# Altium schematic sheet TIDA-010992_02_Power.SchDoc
size 431 x 279 mm; Date: Not shown in title block; ApprovedBy: Not shown in title block; CheckedBy: Not shown in title block; Author: Not shown in title block; CompanyName: Not shown in title block; Engineer: Not shown in title block; Organization: Not shown in title block; Address1: Not shown in title block; Address2: Not shown in title block; Address3: Not shown in title block; Address4: Not shown in title block; DocumentNumber: 2; Revision: Use project parameter SCH_Rev; SheetNumber: 2; SheetTotal: 13; PageSetup: Record=PageOptions¦CenterHorizontal=True¦CenterVertical=True¦PrintScale=1.00¦XCorrection=1.00¦YCorrection=1.00¦PrintKind=0¦BorderSize=5000000¦LeftOffset=0¦BottomOffset=0¦Orientation=2¦PaperLength=1000¦PaperWidth=1000¦Scale=100¦PaperSource=15¦PrintQuality=600¦MediaType=1¦DitherType=10¦PaperKind=Letter¦PrintScaleMode=1
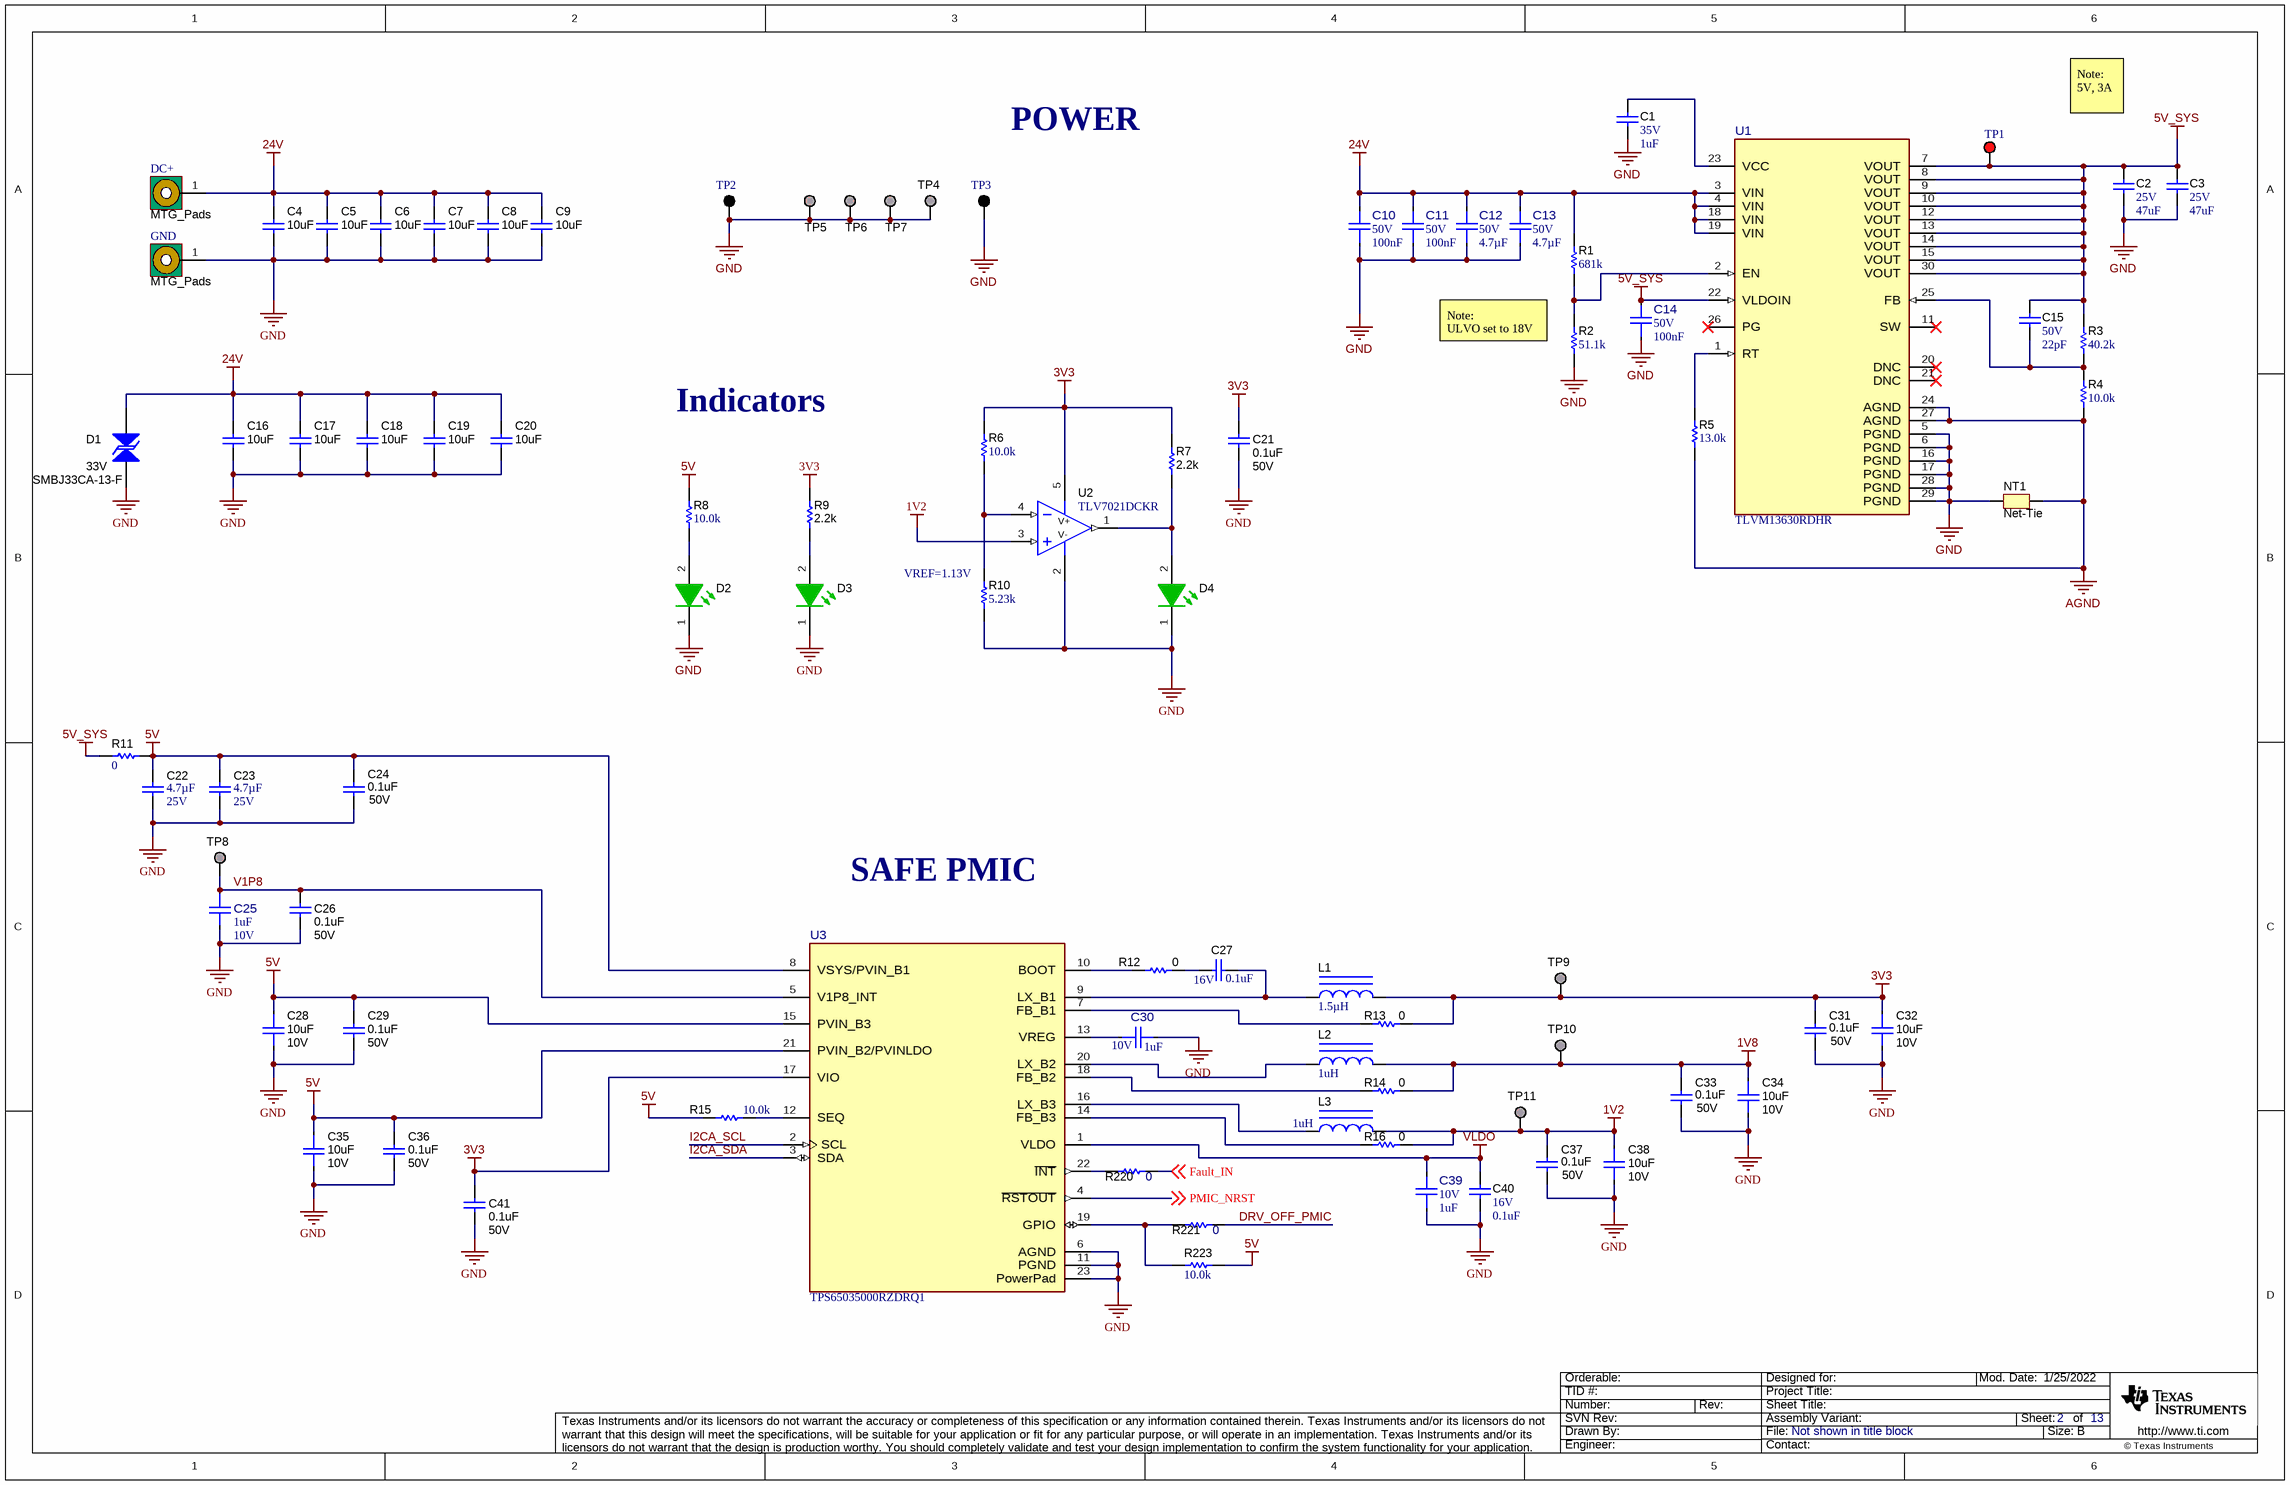
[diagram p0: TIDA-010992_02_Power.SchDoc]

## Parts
C1  VDC_V: 35V  ValueDisplayed: 1uF  [0402L]  (hidden comment: GRM155R6YA105ME11D)
C2  VDC_V: 25V  ValueDisplayed: 47uF  [1206_190]  (hidden comment: C3216X5R1E476M160AC)
C3  VDC_V: 25V  ValueDisplayed: 47uF  [1206_190]  (hidden comment: C3216X5R1E476M160AC)
C4  ValueDisplayed: 10uF  [1210_270L]  (hidden comment: GRM32ER71H106KA12L)
C5  ValueDisplayed: 10uF  [1210_270L]  (hidden comment: GRM32ER71H106KA12L)
C6  ValueDisplayed: 10uF  [1210_270L]  (hidden comment: GRM32ER71H106KA12L)
C7  ValueDisplayed: 10uF  [1210_270L]  (hidden comment: GRM32ER71H106KA12L)
C8  ValueDisplayed: 10uF  [1210_270L]  (hidden comment: GRM32ER71H106KA12L)
C9  ValueDisplayed: 10uF  [1210_270L]  (hidden comment: GRM32ER71H106KA12L)
C10  VDC_V: 50V  ValueDisplayed: 100nF  [FP-885012205086_0402-MFG]  (hidden comment: 885012205086)
C11  VDC_V: 50V  ValueDisplayed: 100nF  [FP-885012205086_0402-MFG]  (hidden comment: 885012205086)
C12  VDC_V: 50V  Cap_F: 4.7µF  [FP-C2012X7R1H475K125AC_0805-MFG]  (hidden comment: C2012X7R1H475K125AC)
C13  VDC_V: 50V  Cap_F: 4.7µF  [FP-C2012X7R1H475K125AC_0805-MFG]  (hidden comment: C2012X7R1H475K125AC)
C14  VDC_V: 50V  ValueDisplayed: 100nF  [FP-885012205086_0402-MFG]  (hidden comment: 885012205086)
C15  VDC_V: 50V  ValueDisplayed: 22pF  [0402L]  (hidden comment: CGA2B2C0G1H220J050BA)
C16  ValueDisplayed: 10uF  [1210_270L]  (hidden comment: GRM32ER71H106KA12L)
C17  ValueDisplayed: 10uF  [1210_270L]  (hidden comment: GRM32ER71H106KA12L)
C18  ValueDisplayed: 10uF  [1210_270L]  (hidden comment: GRM32ER71H106KA12L)
C19  ValueDisplayed: 10uF  [1210_270L]  (hidden comment: GRM32ER71H106KA12L)
C20  ValueDisplayed: 10uF  [1210_270L]  (hidden comment: GRM32ER71H106KA12L)
C21  VDC_V: 50V  ValueDisplayed: 0.1uF  [0402]  (hidden comment: CGA2B3X7R1H104M050BB)
C22  VDC_V: 25V  ValueDisplayed: 4.7µF  [0805L]  (hidden comment: CGA4J1X7R1E475K125AC)
C23  VDC_V: 25V  ValueDisplayed: 4.7µF  [0805L]  (hidden comment: CGA4J1X7R1E475K125AC)
C24  VDC_V: 50V  ValueDisplayed: 0.1uF  [0402]  (hidden comment: CGA2B3X7R1H104M050BB)
C25  VDC_V: 10V  ValueDisplayed: 1uF  [FP-GRM155C71A105KE11D_0402-MFG]  (hidden comment: GRM155C71A105KE11D)
C26  VDC_V: 50V  ValueDisplayed: 0.1uF  [0402]  (hidden comment: CGA2B3X7R1H104M050BB)
C27  VDC_V: 16V  ValueDisplayed: 0.1uF  [0201]  (hidden comment: GRM033Z71C104KE14D)
C28  VDC_V: 10V  ValueDisplayed: 10uF  [FP-CGA4J3X7S1A106K125AE_0805-MFG]  (hidden comment: CGA4J3X7S1A106K125AE)
C29  VDC_V: 50V  ValueDisplayed: 0.1uF  [0402]  (hidden comment: CGA2B3X7R1H104M050BB)
C30  VDC_V: 10V  ValueDisplayed: 1uF  [FP-GRM155C71A105KE11D_0402-MFG]  (hidden comment: GRM155C71A105KE11D)
C31  VDC_V: 50V  ValueDisplayed: 0.1uF  [0402]  (hidden comment: CGA2B3X7R1H104M050BB)
C32  VDC_V: 10V  ValueDisplayed: 10uF  [FP-CGA4J3X7S1A106K125AE_0805-MFG]  (hidden comment: CGA4J3X7S1A106K125AE)
C33  VDC_V: 50V  ValueDisplayed: 0.1uF  [0402]  (hidden comment: CGA2B3X7R1H104M050BB)
C34  VDC_V: 10V  ValueDisplayed: 10uF  [FP-CGA4J3X7S1A106K125AE_0805-MFG]  (hidden comment: CGA4J3X7S1A106K125AE)
C35  VDC_V: 10V  ValueDisplayed: 10uF  [FP-CGA4J3X7S1A106K125AE_0805-MFG]  (hidden comment: CGA4J3X7S1A106K125AE)
C36  VDC_V: 50V  ValueDisplayed: 0.1uF  [0402]  (hidden comment: CGA2B3X7R1H104M050BB)
C37  VDC_V: 50V  ValueDisplayed: 0.1uF  [0402]  (hidden comment: CGA2B3X7R1H104M050BB)
C38  VDC_V: 10V  ValueDisplayed: 10uF  [FP-CGA4J3X7S1A106K125AE_0805-MFG]  (hidden comment: CGA4J3X7S1A106K125AE)
C39  VDC_V: 10V  ValueDisplayed: 1uF  [FP-GRM155C71A105KE11D_0402-MFG]  (hidden comment: GRM155C71A105KE11D)
C40  VDC_V: 16V  ValueDisplayed: 0.1uF  [0201]  (hidden comment: GRM033Z71C104KE14D)
C41  VDC_V: 50V  ValueDisplayed: 0.1uF  [0402]  (hidden comment: CGA2B3X7R1H104M050BB)
D1  SMBJ33CA-13-F  value 33V  [SMB-Bi]
D2  150040GS73240  [WL-SMCC_0402_Green]  (value not drawn)
D3  150040GS73240  [WL-SMCC_0402_Green]  (value not drawn)
D4  150040GS73240  [WL-SMCC_0402_Green]  (value not drawn)
DC+  MTG_Pads  [MTGP_2-48_PanHead]  (no BOM)
GND  MTG_Pads  [MTGP_2-48_PanHead]  (no BOM)
L1  ValueDisplayed: 1.5µH  [TFM201610ALMA]  (hidden comment: TFM201610ALMA1R5MTAA)
L2  ValueDisplayed: 1uH  [TFM201610]  (hidden comment: TFM201610GHM-1R0MTAA)
L3  ValueDisplayed: 1uH  [TFM201610]  (hidden comment: TFM201610GHM-1R0MTAA)
NT1  Net-Tie  [Net-Tie7milsWide_20milsLong]  (net tie, no BOM)
R1  ValueDisplayed: 681k  [0402L]  (hidden comment: CRCW0402681KFKED)
R2  ValueDisplayed: 51.1k  [0402L]  (hidden comment: CRCW040251K1FKED)
R3  ValueDisplayed: 40.2k  [0402L]  (hidden comment: CRCW040240K2FKED)
R4  ValueDisplayed: 10.0k  [0402L]  (hidden comment: CRCW040210K0FKED)
R5  ValueDisplayed: 13.0k  [0402L]  (hidden comment: CRCW040213K0FKED)
R6  ValueDisplayed: 10.0k  [0402L]  (hidden comment: CRCW040210K0FKED)
R7  ValueDisplayed: 2.2k  [0402]  (hidden comment: CRCW04022K20JNED)
R8  ValueDisplayed: 10.0k  [0402L]  (hidden comment: CRCW040210K0FKED)
R9  ValueDisplayed: 2.2k  [0402]  (hidden comment: CRCW04022K20JNED)
R10  ValueDisplayed: 5.23k  [0402]  (hidden comment: CRCW04025K23FKED)
R11  ValueDisplayed: 0  [0603]  (hidden comment: PMR03EZPJ000)
R12  Res_ohm: 0  [FP-RC0201JR-070RL_0201 (0603 Metric)-IPC_C]  (hidden comment: RC0201JR-070RL)
R13  Res_ohm: 0  [FP-RC0201JR-070RL_0201 (0603 Metric)-IPC_C]  (hidden comment: RC0201JR-070RL)
R14  Res_ohm: 0  [FP-RC0201JR-070RL_0201 (0603 Metric)-IPC_C]  (hidden comment: RC0201JR-070RL)
R15  ValueDisplayed: 10.0k  [0402L]  (hidden comment: CRCW040210K0FKED)
R16  Res_ohm: 0  [FP-RC0201JR-070RL_0201 (0603 Metric)-IPC_C]  (hidden comment: RC0201JR-070RL)
R220  ValueDisplayed: 0  [0402]  (hidden comment: CRCW04020000Z0EDHP)
R221  ValueDisplayed: 0  [0402]  (hidden comment: CRCW04020000Z0EDHP)
R223  ValueDisplayed: 10.0k  [0402L]  (hidden comment: CRCW040210K0FKED)
TP1  5000  [Keystone5000]  (value not drawn)
TP2  CMP-0055138-2  [Keystone5001]  (value not drawn)
TP3  CMP-0055138-2  [Keystone5001]  (value not drawn)
TP4  TP_SM_1MM  [TP_SM_1MM]  (value not drawn)  (no BOM)
TP5  TP_SM_1MM  [TP_SM_1MM]  (value not drawn)  (no BOM)
TP6  TP_SM_1MM  [TP_SM_1MM]  (value not drawn)  (no BOM)
TP7  TP_SM_1MM  [TP_SM_1MM]  (value not drawn)  (no BOM)
TP8  TESTPOINT  [TP_25MIL-SMT]  (value not drawn)  (no BOM)
TP9  TESTPOINT  [TP_25MIL-SMT]  (value not drawn)  (no BOM)
TP10  TESTPOINT  [TP_25MIL-SMT]  (value not drawn)  (no BOM)
TP11  TESTPOINT  [TP_25MIL-SMT]  (value not drawn)  (no BOM)
U1  TLVM13630RDHR  [RDH0030A-MFG]
U2  TLV7021DCKR  [DCK0005A_N]
U3  TPS65035000RZDRQ1  [RZD0022A-MFG]

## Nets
1V2: C37.1 C38.1 L3.2 R16.2 TP11.1 U2.3(IN+)
1V8: C33.1 C34.1 L2.2 R14.2 TP10.1
3V3: C21.1 C31.1 C32.1 C41.1 L1.2 R6.1 R7.2 R9.2 R13.2 TP9.1 U2.5(V+) U3.17(VIO)
5V: C22.1 C23.1 C24.1 C28.1 C29.1 C35.1 C36.1 R8.1 R11.1 R15.2 R223.2 U3.8(VSYS/PVIN_B1) U3.15(PVIN_B3) U3.21(PVIN_B2/PVINLDO)
5V_SYS: C2.1 C3.1 C14.2 C15.1 R3.2 R11.2 TP1.1 U1.7(VOUT) U1.8(VOUT) U1.9(VOUT) U1.10(VOUT) U1.12(VOUT) U1.13(VOUT) U1.14(VOUT) U1.15(VOUT) U1.22(VLDOIN) U1.30(VOUT)
24V: C4.2 C5.2 C6.2 C7.2 C8.2 C9.2 C10.2 C11.2 C12.2 C13.2 C16.2 C17.2 C18.2 C19.2 C20.2 D1.2 DC+.1 R1.2 U1.3(VIN) U1.4(VIN) U1.18(VIN) U1.19(VIN)
AGND: NT1.2 R4.1 R5.1 U1.24(AGND) U1.27(AGND)
GND: C1.2 C2.2 C3.2 C4.1 C5.1 C6.1 C7.1 C8.1 C9.1 C10.1 C11.1 C12.1 C13.1 C14.1 C16.1 C17.1 C18.1 C19.1 C20.1 C21.2 C22.2 C23.2 C24.2 C25.2 C26.2 C28.2 C29.2 C30.2 C31.2 C32.2 C33.2 C34.2 C35.2 C36.2 C37.2 C38.2 C39.1 C40.1 C41.2 D1.1 D2.1(K) D3.1(K) D4.1(K) GND.1 NT1.1 R2.1 R10.1 TP2.1 TP3.1 TP4.1 TP5.1 TP6.1 TP7.1 U1.5(PGND) U1.6(PGND) U1.16(PGND) U1.17(PGND) U1.28(PGND) U1.29(PGND) U2.2(V-) U3.6(AGND) U3.11(PGND) U3.23(PowerPad)
VLDO: C39.2 C40.2 U3.1(VLDO)
DRV_OFF_PMIC: R221.2
Fault_IN: R220.2 ; off-sheet Fault_IN
I2CA_SCL: U3.2(SCL)
I2CA_SDA: U3.3(SDA)
PMIC_NRST: U3.4(~{RSTOUT}) ; off-sheet PMIC_NRST
V1P8: C25.1 C26.1 TP8.1 U3.5(V1P8_INT)
NetC1_1: C1.1 U1.23(VCC)
NetC15_2: C15.2 R3.1 R4.2 U1.25(FB)
NetC27_1: C27.1 R12.2
NetC27_2: C27.2 L1.1 U3.9(LX_B1)
NetC30_1: C30.1 U3.13(VREG)
NetD2_2: D2.2(A) R8.2
NetD3_2: D3.2(A) R9.1
NetD4_2: D4.2(A) R7.1 U2.1(OUT)
NetL2_1: L2.1 U3.20(LX_B2)
NetL3_1: L3.1 U3.16(LX_B3)
NetR1_1: R1.1 R2.2 U1.2(EN)
NetR5_2: R5.2 U1.1(RT)
NetR6_2: R6.2 R10.2 U2.4(IN-)
NetR12_1: R12.1 U3.10(BOOT)
NetR13_1: R13.1 U3.7(FB_B1)
NetR14_1: R14.1 U3.18(FB_B2)
NetR15_1: R15.1 U3.12(SEQ)
NetR16_1: R16.1 U3.14(FB_B3)
NetR220_1: R220.1 U3.22(~{INT})
NetR221_1: R221.1 R223.1 U3.19(GPIO)

Not connected (* = marked no-connect by the designer): U1 11(SW)* 20(DNC)* 21(DNC)* 26(PG)*

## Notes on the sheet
- POWER
- Note:
  5V, 3A
- Note:
  ULVO set to 18V
- Indicators
- (near R10) VREF=1.13V
- SAFE PMIC

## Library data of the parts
C1 = CMP-0006620-2: CAP, CERM, 1 uF, 35 V, +/- 20%, X5R, 0402; Manufacturer: MuRata; TaMin_C: -55°C; Polarized: N; SizeAreaWB_mm2: 3; Value1: Unknown; U/M: EA; Value: 1uF; TaMax_C: 85°C; SizeZ_mm: 0.6; SizeX_mm: 1; SizeY_mm: 0.5; Cap_Case: 0402; Cap_F: 1µF; AEC Category: Q200
C2 C3 = CMP-0008656-2: CAP, CERM, 47 uF, 25 V, +/- 20%, X5R, 1206_190; Manufacturer: TDK; TaMin_C: -55°C; Polarized: N; SizeAreaWB_mm2: 10.92; Value1: Unknown; U/M: EA; Value: 47uF; TaMax_C: 85°C; SizeZ_mm: 1.9; SizeX_mm: 3.2; SizeY_mm: 1.6; Cap_Case: 1206; SizeArea_mm2: 5.12; Cap_F: 47µF; AEC Category: Q200
C4-C9 C16-C20 = CMP-0009226-3: CAP, CERM, 10 uF, 50 V, +/- 10%, X7R, 1210; Manufacturer: MuRata; TaMin_C: -55°C; Polarized: N; SizeAreaWB_mm2: 14.7; Value1: Unknown; U/M: EA; Value: 10uF; TaMax_C: 125°C; SizeZ_mm: 2.7; SizeX_mm: 3.2; SizeY_mm: 2.5; Cap_Case: 1210; Value2: 50V; SizeArea_mm2: 8; Cap_F: 10µF; AEC Category: Q200
C10 C11 C14 = CMP-0096737-1: 100 nF ±10% 50V Ceramic Capacitor X7R 0402 (1005 Metric); Manufacturer: Wurth; SizeZ_mm: 0.7mm; TempCo: 15%; AEC Qualified: No; Value: 100nF
C12 C13 = CMP-0088943-1: 4.7µF ±10% 50V Ceramic Capacitor X7R 0805 (2012 Metric); Manufacturer: TDK; TempCo: 15%; AEC Qualified: No; ValueDisplayed: 4.7uF; SizeZ_mm: 1.5mm
C15 = CMP-0860831-1: CAP, CERM, 22 pF, 50 V,+/- 5%, C0G/NP0, AEC-Q200 Grade 1, 0402; Manufacturer: TDK; Cap_Case: 0402; AEC Grade: 1; AEC Category: Q200; TaMin_C: -55°C; SizeY_mm: 0.5; Polarized: N; U/M: EA; SizeZ_mm: 0.6; AEC Qualified: Y; SizeAreaWB_mm2: 3; TaMax_C: 125°C; Value: 22pF
C21 C24 C26 C29 C31 C33 C36 C37 C41 = CMP-0006326-2: CAP, CERM, 0.1 uF, 50 V, +/- 20%, X7R, AEC-Q200 Grade 1, 0402; Manufacturer: TDK; TaMin_C: -55°C; Polarized: N; SizeAreaWB_mm2: 3; Value1: Unknown; U/M: EA; Value: 0.1uF; TaMax_C: 125°C; SizeZ_mm: 0.6; SizeX_mm: 1; SizeY_mm: 0.5; AEC Qualified: Y; Cap_F: 100nF; AEC Category: Q200
C22 C23 = CMP-0076706-1: CAP, CERM, 4.7 µF, 25 V,+/- 10%, X7R, AEC-Q200 Grade 1, 0805; Manufacturer: TDK; TaMin_C: -55°C; Polarized: N; SizeAreaWB_mm2: 6.75; U/M: EA; Value: 4.7uF; TaMax_C: 125°C; SizeZ_mm: 1.45; SizeX_mm: 2.0; SizeY_mm: 1.25; Cap_Case: 2x1.25x1.25mm; SizeArea_mm2: 2.5; AEC Qualified: Y; AEC Grade: 1; AEC Category: Q200
C25 C30 C39 = CMP-0035346-1: 1µF ±10% 10V Ceramic Capacitor X7S 0402 (1005 Metric); Manufacturer: Murata; TempCo: 22%; SizeZ_mm: 0.6mm; AEC Qualified: No
C27 C40 = CMP-0064970-1: CAP, CERM, 0.1 uF, 16 V,+/- 10%, X7R, 0201; Manufacturer: MuRata; TaMin_C: -55°C; Polarized: N; SizeAreaWB_mm2: 2.08; Value1: Unknown; U/M: EA; Value: 0.1uF; TaMax_C: 125°C; SizeZ_mm: 0.26; SizeX_mm: 0.6; SizeY_mm: 0.3; SizeArea_mm2: 0.18; Cap_F: 100nF; AEC Category: Q200
C28 C32 C34 C35 C38 = CMP-0089543-1: 10µF ±10% 10V Ceramic Capacitor X7S 0805 (2012 Metric); Manufacturer: TDK; SizeZ_mm: 1.5mm; AEC Grade: Grade 1; AEC Qualified: Yes; TempCo: 22%
D1 = CMP-0005564-3: Diode, TVS, Bi, 33 V, SMB; Manufacturer: Diodes Inc.; SizeX_mm: 5.6; Ppk: 600W; SizeAreaWB_mm2: 44.156; SizeZ_mm: 2.6; SizeArea_mm2: 21.336; SizeY_mm: 3.81; AEC Category: Q101
D2-D4 = CMP-0081765-2: LED, Green, SMD; Manufacturer: Wurth Elektronik; Vr_V: 5V; Io_A: 20mA; Tjmax_C: 95°C; Ir_A: 10µA; Power_TotalModule: 99mW; Value2: 3.2V; SizeArea_mm2: 0.5; SizeX_mm: 1; Value1: 0.099W; Angle: 120; Type: InGaN; SizeAreaWB_mm2: 3
DC+ GND = CMP-0078421-2: PCB Mounting Hole; Manufacturer: Any; Key: Mounting Hole (Imperial) with Pads
L1 = CMP-0081093-1: Inductor, Shielded, Metal Composite, 1.5 µH, 2.3 A, 0.11 ohm, AEC-Q200 Grade 0, SMD; Manufacturer: TDK; Isat: 2.8A @ 30% inductance drop; Irms: 2.3A @ 40C rise; SizeAreaWB_mm2: 7.8; DCR_ohm: 0.11; Value: 1.5uH; Imax_A: 2.3A; SizeZ_mm: 1; SizeX_mm: 2; SizeY_mm: 1.6; SizeArea_mm2: 3.2; AEC Qualified: Y; AEC Grade: 0; AEC Category: Q200
L2 L3 = CMP-0062877-1: Inductor, 1 uH, 3.1 A, 0.06 ohm, SMD; Manufacturer: TDK; Isat: 3.6A @ 30% inductance drop; Irms: 3.1A @ 40C rise; Green_Lifecycle: Active; SizeAreaWB_mm2: 7.8; DCR_ohm: 60m; Green_REACh: Passed; Value: 1uH; Imax_A: 3.1A; SizeZ_mm: 1; SizeX_mm: 2; SizeY_mm: 1.6; SizeArea_mm2: 3.2; Ind_H: 1µH; AEC Qualified: N; AEC Category: Q200
NT1 = CMP-0078142-5: Single point connection between nets.
R1 = CMP-0026504-2: RES, 681 k, 1%, 0.063 W, AEC-Q200 Grade 0, 0402; Manufacturer: Vishay-Dale; Power_W: 63mW; TempCo: 100 ppm/C; Value: 681k; EIA_Code: E96; SizeX_mm: 1; SizeY_mm: 0.5; SizeZ_mm: 0.6; Value2: 0.063W; AEC Qualified: Y; VDC_V: 50V; AEC Category: Q200; AEC Grade: 0
R2 = CMP-0026437-2: RES, 51.1 k, 1%, 0.063 W, AEC-Q200 Grade 0, 0402; Manufacturer: Vishay-Dale; Power_W: 63mW; TempCo: 100 ppm/C; Value_Code: 51k1; Value: 51.1k; EIA_Code: E96; SizeX_mm: 1; SizeY_mm: 0.5; SizeZ_mm: 0.6; Value2: 0.063W; AEC Qualified: Y; VDC_V: 50V; AEC Category: Q200; AEC Grade: 0
R3 = CMP-0026367-2: RES, 40.2 k, 1%, 0.063 W, AEC-Q200 Grade 0, 0402; Manufacturer: Vishay-Dale; Power_W: 63mW; TempCo: 100 ppm/C; Value_Code: 40k2; Value: 40.2k; EIA_Code: E96; SizeX_mm: 1; SizeY_mm: 0.5; SizeZ_mm: 0.6; Value2: 0.063W; AEC Qualified: Y; VDC_V: 50V; AEC Category: Q200; AEC Grade: 0
R4 R6 R8 R15 R223 = CMP-0025958-3: RES, 10.0 k, 1%, 0.063 W, AEC-Q200 Grade 0, 0402; Manufacturer: Vishay-Dale; Power_W: 63mW; TempCo: 100 ppm/C; Value_Code: 10k0; Value: 10.0k; EIA_Code: E96; Res_ohm: 10k; SizeX_mm: 1; SizeY_mm: 0.5; SizeZ_mm: 0.6; Value2: 0.063W; AEC Qualified: Y; VDC_V: 50V; AEC Category: Q200; AEC Grade: 0
R5 = CMP-0026003-3: RES, 13.0 k, 1%, 0.063 W, AEC-Q200 Grade 0, 0402; Manufacturer: Vishay-Dale; Power_W: 63mW; TempCo: 100 ppm/C; Value_Code: 13k0; Value: 13.0k; EIA_Code: E96; Res_ohm: 13k; SizeX_mm: 1; SizeY_mm: 0.5; SizeZ_mm: 0.6; Value2: 0.063W; AEC Qualified: Y; VDC_V: 50V; AEC Category: Q200; AEC Grade: 0
R7 R9 = CMP-0026890-5: RES, 2.2 k, 5%, 0.063 W, AEC-Q200 Grade 0, 0402; Manufacturer: Vishay-Dale; Value: 2.2k; Value_Code: 2k20; Power_W: 63mW; Value2: 0.063W; VDC_V: 50V; TempCo: 200 ppm/C; SizeArea_mm2: 0.5; SizeX_mm: 1; SizeZ_mm: 0.6; EIA_Code: E24; AEC Category: Q200; AEC Qualified: Y; AEC Grade: 0
R10 = CMP-0026464-2: RES, 5.23 k, 1%, 0.063 W, AEC-Q200 Grade 0, 0402; Manufacturer: Vishay-Dale; Power_W: 63mW; TempCo: 100 ppm/C; Value_Code: 5k23; Value: 5.23k; EIA_Code: E96; SizeX_mm: 1; SizeY_mm: 0.5; SizeZ_mm: 0.6; Value2: 0.063W; AEC Qualified: Y; VDC_V: 50V; AEC Category: Q200; AEC Grade: 0
R11 = CMP-0086358-1: RES, 0, 0%, 0.25 W, AEC-Q200 Grade 0, 0603; Manufacturer: Rohm; Power_W: 250mW; SizeZ_mm: 1; SizeArea_mm2: 1.28; Value2: 0.25W; SizeAreaWB_mm2: 4.68; Value_Code: 0000; Value: 0; AEC Qualified: Y; AEC Category: Q200; SizeX_mm: 1.6; SizeY_mm: 0.8
R12-R14 R16 = CMP-0086442-2: RES SMD 0 OHM JUMPER 1/20W 0201; Manufacturer: Yageo; Power_W: 50mW; VDC_V: 25V; AEC Qualified: No; Tolerance_%: 5%; TempCo: 200ppm/°C; SizeZ_mm: 0.26mm
R220 R221 = CMP-0081856-1: RES, 0, 0%, 0.2 W, AEC-Q200 Grade 0, 0402; Manufacturer: Vishay-Dale; SizeAreaWB_mm2: 3; SizeArea_mm2: 0.5; AEC Qualified: Y; AEC Category: Q200; Value: 0; SizeZ_mm: 0.6; Power_W: 200mW; VDC_V: 50V; Value2: 0.2W; SizeX_mm: 1
TP1 = CMP-0055137-2: Test Point, Miniature, Red, TH; Manufacturer: Keystone Electronics; Green_REACh: Passed; Green_Lifecycle: Active; ContactFinish: Silver; CNHeader: FALSE; CT: TRUE
TP2 TP3 = CMP-0055138-2: Test Point, Miniature, Black, TH; Manufacturer: Keystone Electronics; ContactFinish: Silver; CNHeader: FALSE; Green_Lifecycle: Active; Green_REACh: Passed; CT: TRUE
TP4-TP7 = CMP-0003825-1: 1mm Test Point, SMT; Manufacturer: Any
TP8-TP11 = CMP-0078143-3: TEST POINT.  No entry in BOM.
U1 = CMP-0092030-4: 3-V to 36-V Input, 1-V to 6-V Output, 3-A Power Module; Manufacturer: Texas Instruments; Max Supply Voltage: 36V; Standoff Height: 0mm; AEC Qualified: No; CompType: IC; Min Supply Voltage: 3V; Switching Topology: Buck; AEC Category: Q200; TaMin_C: -40°C; TaMax_C: +105°C; Output Voltage: 1-6V; Switching Frequency: 200-2200kHz; Output Type: AdjustableProgrammable; SizeZ_mm: 1.9mm; Number Of Outputs: 1
U2 = CMP-0085889-2: Small-Size Micropower Low-Voltage Comparator, DCK0005A (SOT-SC70-5); Manufacturer: Texas Instruments; Alternate PartNumber: TLV7021DCKT; SizeAreaWB_mm2: 9.3; SizeY_mm: 2; Rating: Catalog; SizeZ_mm: 1.1; SizeX_mm: 2.1; CompType: IC; AEC Qualified: N; SizeArea_mm2: 4.2; AEC Category: Q200
U3 = CMP-0097122-2: Automotive Camera PMIC; Manufacturer: Texas Instruments; Number Of Outputs: 4; Nominal Supply Current: 10mA; TaMax_C: +125°C; Min Supply Voltage: 2.5V; Output Voltage: 2.5-4/0.9-1.9/1.8-3.3V; Standoff Height: 0mm; TJmax_C: +150°C; SizeZ_mm: 1.05mm; AEC Grade: Grade 1; Max Supply Voltage: 18.3V; TaMin_C: -40°C; AEC Qualified: Yes; AEC Category: Q200; CompType: IC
